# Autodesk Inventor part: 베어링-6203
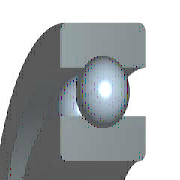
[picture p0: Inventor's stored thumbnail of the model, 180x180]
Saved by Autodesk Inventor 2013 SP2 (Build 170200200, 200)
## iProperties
IsCustomPart: 0
Created: 2016-05
Part Number: 베어링-6203
Material: 강, 연강
Description: 깊은 그루브 볼 베어링
Document SubType Name: Modeling
Standard: KS B 2023
Designer: mduedu
Standards Organization: KS
Language: ko-KR
Size Designation: 6203 - 17 x 40 x 12
Categories: <MemberInstance><Categories><Category DisplayName="샤프트 부품" InternalName="7f7aeb1f-a693-4053-b835-cee3144e0d98" Mnemonic="SHFT"><Category DisplayName="베어링" Inter
Density: 1 g/cm^3
Author: mduedu
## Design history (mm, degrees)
sketch "스케치" dims "d0" = 5.98 (= -0.26 x WD + 0.26 x BD)
  geometry: L1 (3.01, 14.25)-(8.99, 14.25); L2 (6, 14.25)-(6, 11.26); L3 (6, 14.25)-(6, 17.24); L4 (3.778, 12.249)-(0, 12.249); L5 (0, 8.5)-(12, 8.5); L6 (3.778, 16.251)-(0, 16.251); L7 (0, 20)-(12, 20); L8 (12, 8.5)-(12, 12.249); L9 (8.222, 12.249)-(12, 12.249); L10 (8.222, 16.251)-(12, 16.251); L11 (12, 20)-(12, 16.251); L12 (-1.4, 0)-(8.4, 0) reference; L13 (0, -0.3)-(0, 5.3) reference
  constraints: 22 end point, 4 point on line, 2 collinear, 2 perpendicular, 2 symmetric about line, 1 midpoint, 1 parallel, 14 other
  dimensions: "d9" = 17 diameter of L5 L12 (= WD); "d11" = 40 diameter of L7 L12 (= BD); "d12" = 12 distance between parallel lines of L8 L13 (= KB); "d13" = 24.498 diameter of L9 L12 (= 0.326 x BD + 0.674 x WD)
revolve "본체" stored, may be unused: angle "d6" = 90 deg
revolve "볼" stored, may be unused: angle "d7" = 90 deg
pattern_circular "IDS_ARRAYBALL[SIMPL:T]" dims angle "d3" = 360 deg
body "Solid1"
fillet "모깎기1" dims "d1" = 0.6 (= KRS)
other parameters: "WD" = 17 [user parameter; used in 5 equation terms], "BD" = 40 [user parameter; used in 5 equation terms], "KB" = 12 [user parameter; used in 1 equation term], "KRS" = 0.6 [user parameter; used in 1 equation term], "d4" = 0, "d5" = 0, "d8" = 0, "d14" = 0, "d15" = 0, "BBA" = 0 [user parameter], "BC0" = 4750000 [user parameter], "BC" = 9560000 [user parameter], "WR" = 8.5 (= 0.5 x WD) [user parameter]
